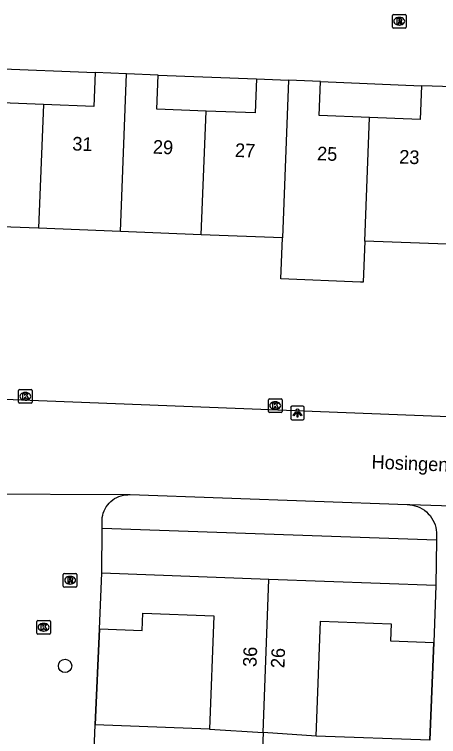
# Model space of a CAD drawing. Extents: x 160787 to 161428, y 386828 to 387483.
# Drawn here: x 161172.8 to 161204, y 387264.6 to 387317.6 of the extents above; entities that cross this region are included whole.
import ezdxf

# ---------------------------------------------------------------- set-up
doc = ezdxf.new("R2010")
doc.units = 0
for name, color, linetype in [('IMGEO_Boom', 7, 'Continuous'), ('IMGEO_Groenvoorziening', 7, 'Continuous'), ('IMGEO_Kolk', 7, 'Continuous'), ('IMGEO_Lichtpunt', 7, 'Continuous'), ('IMGEO_Muur', 7, 'Continuous'), ('IMGEO_Openbare_ruimte_label', 7, 'Continuous'), ('IMGEO_Pand', 7, 'Continuous'), ('IMGEO_Pand_nummerreeks', 7, 'Continuous'), ('IMGEO_Rijbaan_lokaal_open', 7, 'Continuous'), ('IMGEO_Rioolput', 7, 'Continuous'), ('IMGEO_Voetpad_open', 7, 'Continuous')]:
    doc.layers.add(name, color=color, linetype=linetype)

msp = doc.modelspace()

# ---------------------------------------------------------------- linework, layer by layer
at = {"layer": 'IMGEO_Boom'}
msp.add_circle((161176.52, 387269.823), 0.489, dxfattribs=at)
at = {"layer": 'IMGEO_Groenvoorziening'}
msp.add_lwpolyline([(161179.24, 387279.945), (161203.799, 387279.08)], dxfattribs=at)
at = {"layer": 'IMGEO_Kolk'}
for p, q in [((161173.104, 387289.183), (161173.104, 387290.035)), ((161173.179, 387290.109), (161174.031, 387290.109)), ((161173.592, 387289.889), (161173.617, 387289.889)), ((161174.105, 387290.035), (161174.105, 387289.183)), ((161173.615, 387289.329), (161173.59, 387289.329)), ((161191.461, 387288.5), (161191.461, 387289.352)), ((161191.536, 387289.426), (161192.388, 387289.426)), ((161192.462, 387289.352), (161192.462, 387288.5)), ((161174.031, 387289.109), (161173.179, 387289.109)), ((161191.949, 387289.206), (161191.974, 387289.206)), ((161192.388, 387288.426), (161191.536, 387288.426)), ((161191.972, 387288.646), (161191.947, 387288.646)), ((161174.445, 387272.237), (161174.445, 387273.089)), ((161174.52, 387273.163), (161175.372, 387273.163)), ((161174.933, 387272.943), (161174.958, 387272.943)), ((161175.446, 387273.089), (161175.446, 387272.237)), ((161174.956, 387272.383), (161174.931, 387272.383)), ((161175.372, 387272.163), (161174.52, 387272.163))]:
    msp.add_line(p, q, dxfattribs=at)
for points in [[(161173.104, 387289.183), (161173.104, 387290.035)], [(161173.179, 387290.109), (161174.031, 387290.109)], [(161173.425, 387289.809), (161173.548, 387289.809), (161173.548, 387289.658), (161173.678, 387289.809), (161173.842, 387289.809), (161173.696, 387289.658), (161173.849, 387289.409), (161173.697, 387289.409), (161173.612, 387289.573), (161173.548, 387289.506), (161173.548, 387289.409), (161173.425, 387289.409), (161173.425, 387289.809)], [(161174.105, 387290.035), (161174.105, 387289.183)], [(161191.461, 387288.5), (161191.461, 387289.352)], [(161191.536, 387289.426), (161192.388, 387289.426)], [(161192.462, 387289.352), (161192.462, 387288.5)], [(161174.031, 387289.109), (161173.179, 387289.109)], [(161191.782, 387289.126), (161191.905, 387289.126), (161191.905, 387288.975), (161192.035, 387289.126), (161192.199, 387289.126), (161192.053, 387288.975), (161192.206, 387288.726), (161192.054, 387288.726), (161191.969, 387288.89), (161191.905, 387288.823), (161191.905, 387288.726), (161191.782, 387288.726), (161191.782, 387289.126)], [(161192.388, 387288.426), (161191.536, 387288.426)], [(161174.445, 387272.237), (161174.445, 387273.089)], [(161174.52, 387273.163), (161175.372, 387273.163)], [(161174.766, 387272.863), (161174.889, 387272.863), (161174.889, 387272.712), (161175.019, 387272.863), (161175.183, 387272.863), (161175.037, 387272.712), (161175.19, 387272.463), (161175.038, 387272.463), (161174.953, 387272.627), (161174.889, 387272.56), (161174.889, 387272.463), (161174.766, 387272.463), (161174.766, 387272.863)], [(161175.446, 387273.089), (161175.446, 387272.237)], [(161175.372, 387272.163), (161174.52, 387272.163)]]:
    msp.add_lwpolyline(points, dxfattribs=at)
for centre, start, end in [((161173.181, 387290.033), 91.552, 178.448), ((161173.181, 387290.033), 91.552, 178.448), ((161174.029, 387290.033), 1.552, 88.448), ((161174.029, 387290.033), 1.552, 88.448), ((161191.538, 387289.35), 91.552, 178.448), ((161191.538, 387289.35), 91.552, 178.448), ((161192.386, 387289.35), 1.552, 88.448), ((161192.386, 387289.35), 1.552, 88.448), ((161173.181, 387289.185), 181.552, 268.448), ((161173.181, 387289.185), 181.552, 268.448), ((161174.029, 387289.185), 271.552, 358.448), ((161174.029, 387289.185), 271.552, 358.448), ((161191.538, 387288.502), 181.552, 268.448), ((161191.538, 387288.502), 181.552, 268.448), ((161192.386, 387288.502), 271.552, 358.448), ((161192.386, 387288.502), 271.552, 358.448), ((161174.522, 387273.087), 91.552, 178.448), ((161174.522, 387273.087), 91.552, 178.448), ((161175.37, 387273.087), 1.552, 88.448), ((161175.37, 387273.087), 1.552, 88.448), ((161174.522, 387272.239), 181.552, 268.448), ((161174.522, 387272.239), 181.552, 268.448), ((161175.37, 387272.239), 271.552, 358.448), ((161175.37, 387272.239), 271.552, 358.448)]:
    msp.add_arc(centre, 0.0765, start, end, dxfattribs=at)
for centre, major_axis, ratio, start_param, end_param in [((161173.591, 387289.609), (-0.387, 0.002), 0.722429, 4.712389, 7.853982), ((161173.616, 387289.609), (-0.39, 0.002), 0.717154, 1.570796, 4.712389), ((161191.948, 387288.926), (-0.387, 0.002), 0.722429, 4.712389, 7.853982), ((161191.973, 387288.926), (-0.39, 0.002), 0.717154, 1.570796, 4.712389), ((161174.932, 387272.663), (-0.387, 0.002), 0.722429, 4.712389, 7.853982), ((161174.957, 387272.663), (-0.39, 0.002), 0.717154, 1.570796, 4.712389)]:
    msp.add_ellipse(centre, major_axis=major_axis, ratio=ratio, start_param=start_param, end_param=end_param, dxfattribs=at)
at = {"layer": 'IMGEO_Lichtpunt'}
for p, q in [((161193.097, 387288.796), (161193.097, 387287.989)), ((161193.097, 387288.796), (161193.097, 387287.989)), ((161193.999, 387288.891), (161193.191, 387288.891)), ((161193.999, 387288.891), (161193.191, 387288.891)), ((161194.093, 387287.989), (161194.093, 387288.796)), ((161194.093, 387287.989), (161194.093, 387288.796)), ((161193.191, 387287.895), (161193.999, 387287.895)), ((161193.191, 387287.895), (161193.999, 387287.895))]:
    msp.add_line(p, q, dxfattribs=at)
for points in [[(161193.471, 387288.46), (161193.51, 387288.432), (161193.322, 387288.17), (161193.284, 387288.197), (161193.471, 387288.46)], [(161193.573, 387288.412), (161193.62, 387288.412), (161193.62, 387288.09), (161193.573, 387288.09), (161193.573, 387288.412)], [(161193.683, 387288.432), (161193.721, 387288.459), (161193.908, 387288.197), (161193.869, 387288.169), (161193.683, 387288.432)]]:
    msp.add_lwpolyline(points, dxfattribs=at)
msp.add_circle((161193.596, 387288.594), 0.0994, dxfattribs=at)
for centre, start, end in [((161193.191, 387288.796), 90, 180), ((161193.191, 387288.796), 90, 180), ((161193.999, 387288.796), 0, 90), ((161193.999, 387288.796), 0, 90), ((161193.191, 387287.989), 180, 270), ((161193.191, 387287.989), 180, 270), ((161193.999, 387287.989), 270, 0), ((161193.999, 387287.989), 270, 360)]:
    msp.add_arc(centre, 0.0946, start, end, dxfattribs=at)
at = {"layer": 'IMGEO_Muur'}
for points in [[(161179.064, 387272.548), (161178.724, 387265.502)], [(161203.32, 387264.366), (161203.604, 387271.548)]]:
    msp.add_lwpolyline(points, dxfattribs=at)
at = {"layer": 'IMGEO_Pand'}
for points in [[(161174.935, 387311.032), (161171.246, 387311.176), (161171.343, 387313.673)], [(161178.722, 387313.364), (161178.626, 387310.887), (161174.935, 387311.032)], [(161181.045, 387313.274), (161178.722, 387313.364)], [(161180.592, 387301.703), (161181.045, 387313.274)], [(161183.372, 387313.183), (161181.045, 387313.274)], [(161186.888, 387310.544), (161183.274, 387310.685), (161183.372, 387313.183)], [(161190.597, 387312.897), (161190.5, 387310.403), (161186.888, 387310.544)], [(161190.597, 387312.897), (161192.938, 387312.805)], [(161192.938, 387312.805), (161192.486, 387301.238)], [(161195.279, 387312.713), (161192.938, 387312.805)], [(161198.895, 387310.078), (161195.181, 387310.224), (161195.279, 387312.713)], [(161202.704, 387312.406), (161202.608, 387309.933), (161198.895, 387310.078)], [(161205.032, 387312.315), (161202.704, 387312.406)], [(161174.935, 387311.032), (161174.579, 387301.938)], [(161186.533, 387301.471), (161186.888, 387310.544)], [(161198.54, 387301.001), (161198.895, 387310.078)], [(161174.579, 387301.938), (161168.48, 387302.177)], [(161180.592, 387301.703), (161174.579, 387301.938)], [(161186.533, 387301.471), (161180.592, 387301.703)], [(161192.486, 387301.238), (161186.533, 387301.471)], [(161198.54, 387301.001), (161198.422, 387297.987), (161198.229, 387297.995), (161192.368, 387298.224), (161192.486, 387301.238)], [(161204.58, 387300.765), (161198.54, 387301.001)], [(161179.064, 387272.548), (161179.214, 387276.624)], [(161191.488, 387276.172), (161179.214, 387276.624)], [(161191.064, 387264.932), (161191.488, 387276.172)], [(161203.758, 387275.72), (161191.488, 387276.172)], [(161203.758, 387275.72), (161203.604, 387271.548)], [(161179.064, 387272.548), (161182.199, 387272.432), (161182.245, 387273.702), (161187.441, 387273.51), (161187.135, 387265.192)], [(161194.971, 387264.673), (161195.282, 387273.116), (161200.481, 387272.924), (161200.434, 387271.665), (161203.604, 387271.548)], [(161178.566, 387261.216), (161178.724, 387265.502)], [(161187.135, 387265.192), (161178.724, 387265.502)], [(161187.135, 387265.192), (161191.064, 387264.932)], [(161191.064, 387264.932), (161190.639, 387253.67)], [(161194.971, 387264.673), (161191.064, 387264.932)], [(161203.32, 387264.366), (161194.971, 387264.673)]]:
    msp.add_lwpolyline(points, dxfattribs=at)
at = {"layer": 'IMGEO_Rijbaan_lokaal_open'}
for points in [[(161171.343, 387313.673), (161178.722, 387313.364)], [(161183.372, 387313.183), (161190.597, 387312.897)], [(161195.279, 387312.713), (161202.704, 387312.406)]]:
    msp.add_lwpolyline(points, dxfattribs=at)
at = {"layer": 'IMGEO_Rioolput'}
for p, q in [((161200.571, 387316.707), (161200.571, 387317.559)), ((161200.646, 387317.633), (161201.498, 387317.633)), ((161201.059, 387317.413), (161201.084, 387317.413)), ((161201.572, 387317.559), (161201.572, 387316.707)), ((161201.082, 387316.853), (161201.057, 387316.853)), ((161201.498, 387316.633), (161200.646, 387316.633)), ((161176.469, 387276.614), (161177.321, 387276.614)), ((161176.394, 387275.688), (161176.394, 387276.54)), ((161176.882, 387276.394), (161176.907, 387276.394)), ((161177.395, 387276.54), (161177.395, 387275.688)), ((161177.321, 387275.614), (161176.469, 387275.614)), ((161176.905, 387275.834), (161176.88, 387275.834))]:
    msp.add_line(p, q, dxfattribs=at)
for points in [[(161200.571, 387316.707), (161200.571, 387317.559)], [(161200.646, 387317.633), (161201.498, 387317.633)], [(161201.572, 387317.559), (161201.572, 387316.707)], [(161201.16, 387317.331), (161200.908, 387317.333), (161200.908, 387316.933)], [(161200.908, 387316.933), (161201.032, 387316.933), (161201.032, 387317.095), (161201.043, 387317.095)], [(161201.086, 387317.252), (161201.032, 387317.252), (161201.032, 387317.171)], [(161201.032, 387317.171), (161201.084, 387317.171)], [(161201.09, 387317.066), (161201.161, 387316.933), (161201.301, 387316.933), (161201.236, 387317.059)], [(161201.498, 387316.633), (161200.646, 387316.633)], [(161176.469, 387276.614), (161177.321, 387276.614)], [(161176.394, 387275.688), (161176.394, 387276.54)], [(161176.983, 387276.312), (161176.731, 387276.314), (161176.731, 387275.914)], [(161176.731, 387275.914), (161176.855, 387275.914), (161176.855, 387276.076), (161176.866, 387276.076)], [(161176.909, 387276.233), (161176.855, 387276.233), (161176.855, 387276.152)], [(161176.855, 387276.152), (161176.907, 387276.152)], [(161176.913, 387276.047), (161176.984, 387275.914), (161177.124, 387275.914), (161177.059, 387276.04)], [(161177.395, 387276.54), (161177.395, 387275.688)], [(161177.321, 387275.614), (161176.469, 387275.614)]]:
    msp.add_lwpolyline(points, dxfattribs=at)
for centre, radius, start, end in [((161200.648, 387317.557), 0.0765, 91.552, 178.448), ((161200.648, 387317.557), 0.0765, 91.552, 178.448), ((161201.496, 387317.557), 0.0765, 1.552, 88.448), ((161201.496, 387317.557), 0.0765, 1.552, 88.448), ((161201.042, 387317.042), 0.0533, 26.0293, 88.6989), ((161201.068, 387317.36), 0.19, 274.7715, 282.9687), ((161201.092, 387317.156), 0.0964, 77.0061, 93.1865), ((161201.106, 387317.213), 0.0378, 276.6634, 79.6772), ((161201.159, 387317.221), 0.109, 350.3612, 89.416), ((161201.157, 387317.221), 0.112, 277.5842, 350.9817), ((161201.141, 387317.006), 0.108, 29.5134, 73.7905), ((161200.648, 387316.709), 0.0765, 181.552, 268.448), ((161200.648, 387316.709), 0.0765, 181.552, 268.448), ((161201.496, 387316.709), 0.0765, 271.552, 358.448), ((161201.496, 387316.709), 0.0765, 271.552, 358.448), ((161176.471, 387276.538), 0.0765, 91.552, 178.448), ((161176.471, 387276.538), 0.0765, 91.552, 178.448), ((161177.319, 387276.538), 0.0765, 1.552, 88.448), ((161177.319, 387276.538), 0.0765, 1.552, 88.448), ((161176.865, 387276.023), 0.0533, 26.0293, 88.6989), ((161176.891, 387276.341), 0.19, 274.7715, 282.9687), ((161176.915, 387276.137), 0.0964, 77.0061, 93.1865), ((161176.929, 387276.194), 0.0378, 276.6634, 79.6772), ((161176.982, 387276.202), 0.109, 350.3612, 89.416), ((161176.98, 387276.202), 0.112, 277.5842, 350.9817), ((161176.964, 387275.987), 0.108, 29.5134, 73.7905), ((161176.471, 387275.69), 0.0765, 181.552, 268.448), ((161176.471, 387275.69), 0.0765, 181.552, 268.448), ((161177.319, 387275.69), 0.0765, 271.552, 358.448), ((161177.319, 387275.69), 0.0765, 271.552, 358.448)]:
    msp.add_arc(centre, radius, start, end, dxfattribs=at)
for centre, major_axis, ratio, start_param, end_param in [((161201.058, 387317.133), (-0.387, 0.002), 0.722429, 4.712389, 7.853982), ((161201.083, 387317.133), (-0.39, 0.002), 0.717154, 1.570796, 4.712389), ((161176.881, 387276.114), (-0.387, 0.002), 0.722429, 4.712389, 7.853982), ((161176.906, 387276.114), (-0.39, 0.002), 0.717154, 1.570796, 4.712389)]:
    msp.add_ellipse(centre, major_axis=major_axis, ratio=ratio, start_param=start_param, end_param=end_param, dxfattribs=at)
at = {"layer": 'IMGEO_Voetpad_open'}
for points in [[(161170.163, 387289.466), (161204.081, 387288.161), (161247.486, 387286.367), (161267.914, 387285.628)], [(161181.145, 387282.379), (161169.71, 387282.428)], [(161179.24, 387279.945), (161179.243, 387280.377), (161179.243, 387280.54), (161179.258, 387280.711), (161179.288, 387280.88), (161179.333, 387281.046), (161179.393, 387281.207), (161179.466, 387281.362), (161179.554, 387281.51), (161179.654, 387281.649), (161179.766, 387281.779), (161179.89, 387281.898), (161180.023, 387282.006), (161180.166, 387282.101), (161180.317, 387282.184), (161180.474, 387282.252), (161180.637, 387282.306), (161180.804, 387282.346), (161180.974, 387282.37), (161181.145, 387282.379)], [(161201.851, 387281.648), (161201.652, 387281.657), (161181.317, 387282.373), (161181.145, 387282.379)], [(161211.164, 387281.363), (161201.851, 387281.648)], [(161201.851, 387281.648), (161202.041, 387281.623), (161202.229, 387281.58), (161202.412, 387281.521), (161202.589, 387281.445), (161202.758, 387281.354), (161202.919, 387281.249), (161203.069, 387281.129), (161203.209, 387280.997), (161203.336, 387280.852), (161203.449, 387280.697), (161203.548, 387280.532), (161203.632, 387280.359), (161203.701, 387280.18), (161203.753, 387279.994), (161203.788, 387279.805), (161203.806, 387279.614), (161203.799, 387279.08)], [(161179.214, 387276.624), (161179.24, 387279.945)], [(161203.799, 387279.08), (161203.758, 387275.72)], [(161178.724, 387265.502), (161179.064, 387272.548)], [(161203.604, 387271.548), (161203.32, 387264.366)]]:
    msp.add_lwpolyline(points, dxfattribs=at)

# ---------------------------------------------------------------- texts
at = {"layer": 'IMGEO_Openbare_ruimte_label'}
msp.add_text('Hosingenhof', height=1, rotation=357.7644, dxfattribs=at).set_placement((161199.024, 387284.305))
at = {"layer": 'IMGEO_Pand_nummerreeks'}
for s, rotation, p in [('31', 357.7066, (161177.039, 387307.659)), ('29', 357.7066, (161182.957, 387307.423)), ('27', 357.7066, (161188.989, 387307.181)), ('25', 357.7082, (161195.019, 387306.94)), ('23', 357.7066, (161201.052, 387306.698)), ('36', 87.8937, (161190.584, 387269.733)), ('26', 87.929, (161192.637, 387269.642))]:
    msp.add_text(s, height=1, rotation=rotation, dxfattribs=at).set_placement(p)

doc.saveas('drawing.dxf')
